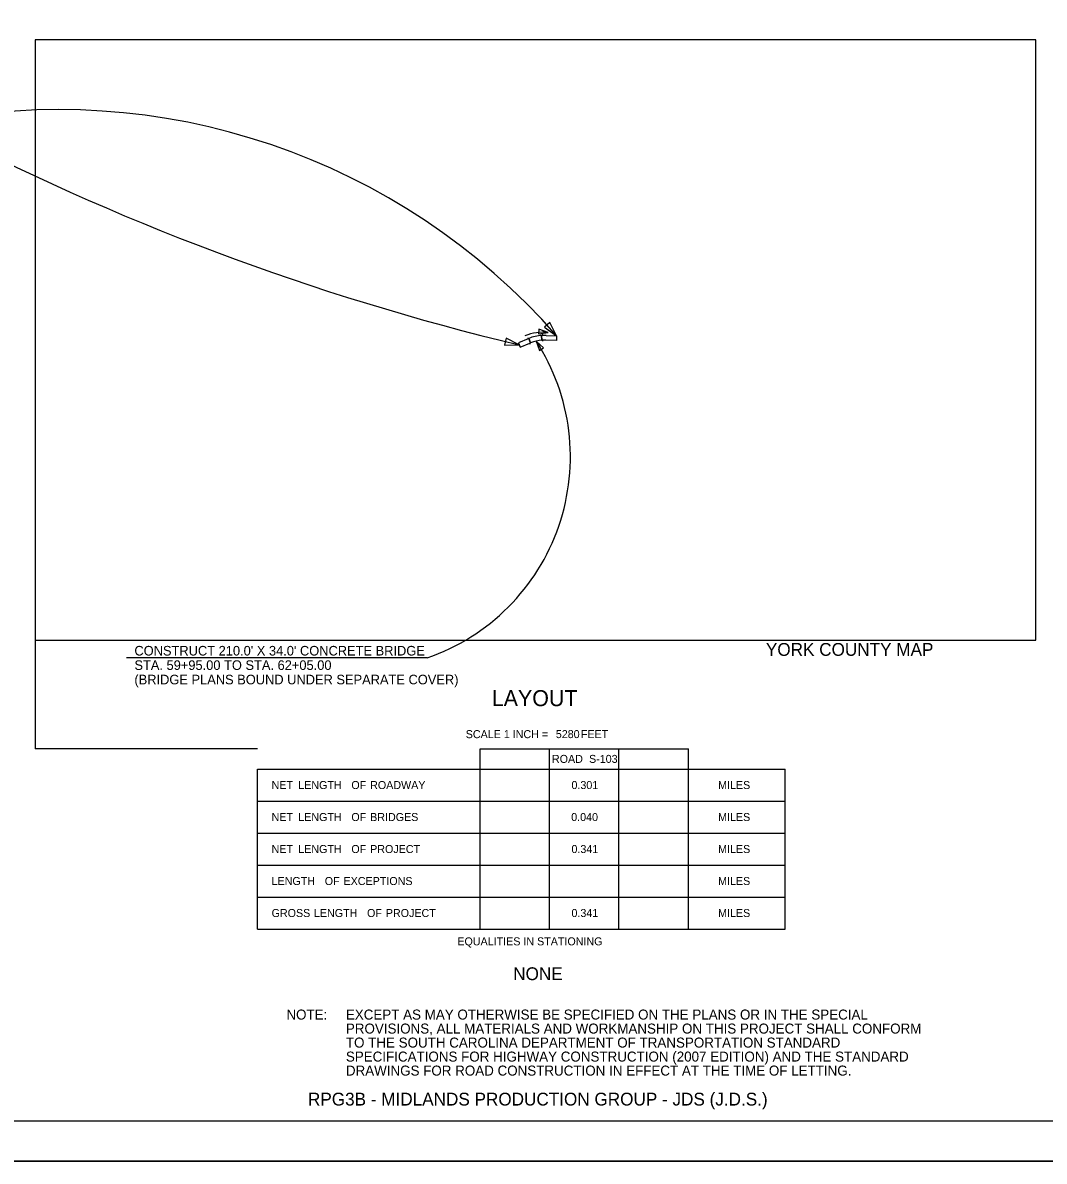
# Model space of a CAD drawing. Extents: x -796 to 2793, y -4650 to 4425.
# Drawn here: x 1596 to 2234, y 1000 to 1711 of the extents above; entities that cross this region are included whole.
import ezdxf

# ---------------------------------------------------------------- set-up
doc = ezdxf.new("R2010")
doc.units = 0
for name, color, linetype in [('RD_EX_Road', 7, 'Continuous'), ('RD_HC_CL', 7, 'Continuous'), ('RD_HC_Data', 7, 'Continuous'), ('RD_HC_Data_Tic', 7, 'Continuous'), ('RD_SHT_Bndy', 7, 'Continuous'), ('RD_Sketch7', 7, 'Continuous'), ('RD_Sketch8', 7, 'Continuous')]:
    doc.layers.add(name, color=color, linetype=linetype)

msp = doc.modelspace()

# ---------------------------------------------------------------- linework, layer by layer
at = {"layer": 'RD_EX_Road'}
msp.add_lwpolyline([(1603.73, 1325.6), (2228.73, 1325.6), (2228.73, 1700.6), (1603.73, 1700.6)], close=True, dxfattribs=at)
at = {"layer": 'RD_HC_CL'}
msp.add_lwpolyline([(984.13, 2100), (2780.13, 2100), (2780.13, 1000), (984.13, 1000)], close=True, dxfattribs=at)
at = {"layer": 'RD_HC_Data'}
for p, q in [((1603.73, 1325.6), (1603.73, 1257.68)), ((1742.67, 1257.68), (1603.73, 1257.68)), ((1742.67, 1257.68), (1742.67, 1257.68)), ((1881.61, 1257.68), (2011.77, 1257.68)), ((1881.61, 1145.07), (1881.61, 1257.68)), ((1925, 1145.07), (1925, 1257.68)), ((1968.38, 1145.07), (1968.38, 1257.68)), ((2011.77, 1145.07), (2011.77, 1257.68)), ((1742.67, 1245), (2072.22, 1245)), ((1742.67, 1145.07), (1742.67, 1245)), ((2072.22, 1145.07), (2072.22, 1245)), ((1742.67, 1225.02), (2072.22, 1225.02)), ((1742.67, 1205.03), (2072.22, 1205.03)), ((1742.67, 1185.04), (2072.22, 1185.04)), ((1742.67, 1165.05), (2072.22, 1165.05)), ((1742.67, 1145.07), (2072.22, 1145.07)), ((2760, 1000), (1000, 1000)), ((1000, 1000), (2759.98, 1000))]:
    msp.add_line(p, q, dxfattribs=at)
msp.add_lwpolyline([(1079.63, 2075.05), (2755.13, 2075.05), (2755.13, 1025), (1079.63, 1025)], close=True, dxfattribs=at)
at = {"layer": 'RD_SHT_Bndy'}
for p, q in [((1925.21, 1523.92), (1921.82, 1520.96)), ((1929.44, 1515.66), (1925.21, 1523.92)), ((1918.41, 1519.86), (1918.06, 1516.88)), ((1918.06, 1516.88), (1924.19, 1517.67)), ((1924.19, 1517.67), (1918.41, 1519.86)), ((1921.82, 1520.96), (1929.44, 1515.66)), ((1897.92, 1514.22), (1896.87, 1509.85)), ((1896.87, 1509.85), (1906.15, 1509.94)), ((1906.15, 1509.94), (1897.92, 1514.22)), ((1916.71, 1512.35), (1918.71, 1506.5)), ((1921.23, 1508.13), (1916.71, 1512.35)), ((1918.71, 1506.5), (1921.23, 1508.13)), ((1848.62, 1314.42), (1660.77, 1314.42))]:
    msp.add_line(p, q, dxfattribs=at)
for centre, radius, start, end in [((1618.5, 1244.15), 412.8, 41.12808, 101.44517), ((2277.64, 3060.42), 1594.36, 242.30321, 256.52616), ((1920.78, 1488.36), 29.52, 83.35386, 112.02244), ((1805.06, 1440.08), 133, 289.11885, 32.91618)]:
    msp.add_arc(centre, radius, start, end, dxfattribs=at)
at = {"layer": 'RD_Sketch7'}
for p, q in [((1920.75, 1516.62), (1920.09, 1515.87)), ((1920.09, 1515.87), (1920.29, 1512.87)), ((1911.23, 1514.47), (1912.14, 1514.07)), ((1912.14, 1514.07), (1913.25, 1511.28)), ((1912.85, 1510.37), (1913.25, 1511.28)), ((1921.05, 1512.22), (1920.29, 1512.87))]:
    msp.add_line(p, q, dxfattribs=at)
for radius in [26.5, 23.5]:
    msp.add_arc((1921.88, 1489.43), radius, 93.88226, 111.56824, dxfattribs=at)
at = {"layer": 'RD_Sketch8'}
for p, q in [((1920.29, 1512.87), (1920.09, 1515.87)), ((1913.25, 1511.28), (1912.14, 1514.07))]:
    msp.add_line(p, q, dxfattribs=at)
for points in [[(1922.88, 1515.91), (1929.44, 1515.66), (1929.32, 1512.67), (1922.76, 1512.91)], [(1911.64, 1513.87), (1905.57, 1511.32), (1906.73, 1508.56), (1912.8, 1511.1)]]:
    msp.add_lwpolyline(points, dxfattribs=at)
for radius, start, end in [(26.5, 87.85793, 93.88226), (26.5, 111.56824, 112.74093), (23.5, 111.56824, 112.74093), (23.5, 87.85793, 93.88226)]:
    msp.add_arc((1921.88, 1489.43), radius, start, end, dxfattribs=at)

# ---------------------------------------------------------------- texts
at = {"layer": 'RD_HC_Data_Tic'}
for s, height, p in [('LAYOUT', 10, (1888.97, 1284.3)), ('SCALE 1 INCH =           FEET', 5, (1872.7, 1264.3)), ('ROAD', 5, (1926.54, 1248.84)), (' S-103', 5, (1947.86, 1248.84)), (' LENGTH', 5, (1766.24, 1232.51)), (' OF', 5, (1799.41, 1232.51)), (' ROADWAY', 5, (1811.14, 1232.51)), ('0.301', 5, (1938.73, 1232.51)), ('MILES', 5, (2030.31, 1232.51)), ('NET', 5, (1751.45, 1232.51)), ('NET', 5, (1751.45, 1212.52)), (' LENGTH', 5, (1766.24, 1212.52)), (' OF', 5, (1799.41, 1212.52)), (' BRIDGES', 5, (1811.14, 1212.52)), ('0.040', 5, (1938.58, 1212.52)), ('MILES', 5, (2030.31, 1212.52)), ('NET', 5, (1751.45, 1192.53)), (' LENGTH', 5, (1766.24, 1192.53)), (' OF', 5, (1799.41, 1192.53)), (' PROJECT', 5, (1811.14, 1192.53)), ('0.341', 5, (1938.73, 1192.53)), ('MILES', 5, (2030.31, 1192.53)), ('LENGTH', 5, (1751.45, 1172.55)), (' OF', 5, (1782.78, 1172.55)), (' EXCEPTIONS', 5, (1794.51, 1172.55)), ('MILES', 5, (2030.31, 1172.55)), ('GROSS', 5, (1751.45, 1152.56)), (' LENGTH', 5, (1776.04, 1152.56)), (' OF', 5, (1809.21, 1152.56)), (' PROJECT', 5, (1820.94, 1152.56)), ('0.341', 5, (1938.73, 1152.56)), ('MILES', 5, (2030.31, 1152.56)), ('EQUALITIES IN STATIONING', 5.0001, (1867.47, 1134.85)), ('NOTE:     EXCEPT AS MAY OTHERWISE BE SPECIFIED ON THE PLANS OR IN THE SPECIAL ', 6.2499, (1760.7, 1088.5)), ('                PROVISIONS, ALL MATERIALS AND WORKMANSHIP ON THIS PROJECT SHALL CONFORM ', 6.2499, (1760.7, 1079.75)), ('                TO THE SOUTH CAROLINA DEPARTMENT OF TRANSPORTATION STANDARD ', 6.2499, (1760.7, 1071)), ('                SPECIFICATIONS FOR HIGHWAY CONSTRUCTION (2007 EDITION) AND THE STANDARD', 6.2499, (1760.7, 1062.25)), ('                DRAWINGS FOR ROAD CONSTRUCTION IN EFFECT AT THE TIME OF LETTING.', 6.2499, (1760.7, 1053.5))]:
    msp.add_text(s, height=height, dxfattribs=at).set_placement(p)
at = {"layer": 'RD_SHT_Bndy'}
for s, height, p in [('YORK COUNTY MAP', 8, (2060.18, 1315.73)), ("CONSTRUCT 210.0' X 34.0' CONCRETE BRIDGE", 6, (1665.77, 1315.92)), ('STA. 59+95.00 TO STA. 62+05.00', 6, (1665.77, 1306.92)), ('(BRIDGE PLANS BOUND UNDER SEPARATE COVER)', 6, (1665.77, 1297.92)), ('5280', 5, (1928.96, 1264.34)), ('NONE', 8, (1902.35, 1113.14)), ('RPG3B - MIDLANDS PRODUCTION GROUP - JDS (J.D.S.)', 8, (1774.18, 1034.8))]:
    msp.add_text(s, height=height, dxfattribs=at).set_placement(p)

doc.saveas('drawing.dxf')
